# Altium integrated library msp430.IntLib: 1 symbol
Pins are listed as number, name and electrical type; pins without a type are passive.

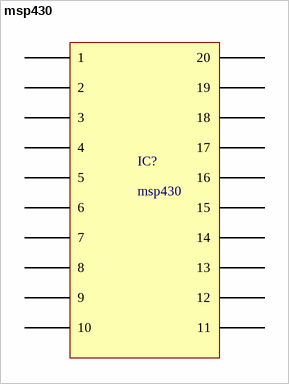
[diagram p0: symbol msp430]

## msp430
designator IC?
footprint msp430
pins: 1, 2, 3, 4, 5, 6, 7, 8, 9, 10, 11, 12, 13, 14, 15, 16, 17, 18, 19, 20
